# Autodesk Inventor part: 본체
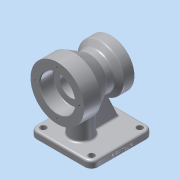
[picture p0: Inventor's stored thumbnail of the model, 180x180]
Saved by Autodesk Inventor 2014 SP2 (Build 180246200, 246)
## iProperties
Created: 2019-01
Part Number: 본체
Material: 알루미늄 6061
Document SubType Name: Modeling
Designer: 거성
Density: 2.71 g/cm^3
Appearance: 알루미늄 - 평지
Mass: 896.056 g
Surface Area: 602.368 cm^2
Volume: 330.648 cm^3
Author: 거성
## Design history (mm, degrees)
sketch "스케치1"
  geometry: L1 (44.102, 40)-(44.102, 15); L2 (39.102, -40)-(39.102, -25); L3 (39.102, -25)-(30.944, -18.154); L4 (30.944, -18.154)-(30.944, -7.791); L5 (30.944, -7.791)-(44.102, 15); L6 (20.102, 20)-(20.102, -23); L7 (24.102, -23)-(24.102, -40); L8 (30.102, 20)-(30.102, 40); L9 (4.102, -40)-(4.102, 40); L10 (20.102, -23)-(24.102, -23); L11 (20.102, 20)-(30.102, 20); L12 (30.102, 40)-(44.102, 40); L13 (39.102, -40)-(24.102, -40)
  constraints: 26 end point, 4 parallel, 3 perpendicular, 2 horizontal
  dimensions: "d2" = 25 distance of L1.start L1.end; "d3" = 30 deg angle of L4 L5; "d4" = 15 distance of L2.start L2.end; "d5" = 50 deg angle of L4 L3; "d6" = 52 diameter of L8 L9; "d7" = 32 diameter of L6 L9; "d8" = 40 diameter of L7 L9; "d9" = 80 vertical distance of L2.start L1.start; "d10" = 20 distance of L8.start L8.end; "d11" = 17 distance of L7.start L7.end; "d20" = 80 distance from line of L9.start L12; "d25" = 80 diameter of L1 L9; "d26" = 70 diameter of L2 L9; "d27" = 13.15845 distance between parallel lines of L4 L1; "d28" = 47.14102 distance from line of L9.end L5
revolve "회전1" sketch "스케치1" stored, may be unused: angle "d23" = 90 deg
sketch "스케치2"
  geometry: C1 r 40 at (0, 0) reference; C2 r 26 at (0, 0) reference; 1 further point
sketch "스케치3" dims "d24" = 66
  geometry: L1 (0, 0)-(0, 33); C1 r 26 at (0, 0) reference; 2 further points
  constraints: 2 coincident, 2 end point, 1 vertical, 1 vertical alignment, 2 other
hole "구멍1" sketch "스케치3" at (0, 33) diameter "d29" = 3.242; stored, may be unused: countersink angle "d33" = 90 deg, drill point angle "d35" = 118 deg; dims "d30" = 9, "d31" = 4, "d32" = 2, "d34" = 11
sketch "스케치4" dims "d39" = 55
  geometry: L1 (0, 0)-(0, 27.5); C1 r 35 at (0, 0) reference; 2 further points
  constraints: 2 coincident, 2 end point, 1 vertical, 1 vertical alignment, 2 other
hole "구멍2" sketch "스케치4" at (0, 27.5) diameter "d40" = 3.242; stored, may be unused: countersink angle "d44" = 90 deg, drill point angle "d46" = 118 deg; dims "d41" = 9, "d42" = 4, "d43" = 2, "d45" = 11
node "작업 평면1"
sketch "스케치7"
  geometry: L1 (-70, -36)-(-70, 36) reference; L2 (-70, 0)-(-70, -33.507); 1 further point
  constraints: 2 end point, 1 collinear, 1 midpoint
chamfer "모따기1" distance "d78" = 1; stored, may be unused: second distance "d79" = 2, angle "d80" = 45 deg
fillet "모깎기2" dims "d81" = 1
fillet "모깎기3" dims "d82" = 0.6
sketch "스케치11"
  geometry: L1 (-75.898, 0)-(-75.898, 35); L2 (-75.898, 35)-(-65.898, 35); L3 (-65.898, 35)-(-65.898, -57); L4 (-65.898, -57)-(-75.898, -57); L5 (-75.898, -57)-(-75.898, 0); L6 (-35.898, 40)-(44.102, 40) reference; L7 (44.102, 15)-(30.944, -7.791) reference; L8 (30.944, -7.791)-(30.944, -18.154) reference; L9 (30.944, -18.154)-(39.102, -25) reference; L10 (39.102, -25)-(39.102, -40) reference; L11 (39.102, -40)-(33.223, -40) reference; L12 (33.223, -40)-(33.223, -29) reference; L13 (33.223, -29)-(31.602, -28.026) reference; L14 (31.602, -28.026)-(29.981, -29) reference; L15 (29.981, -29)-(29.981, -40) reference; L16 (29.981, -40)-(25.102, -40) reference; L17 (25.102, -40)-(24.102, -39) reference; L18 (24.102, -39)-(24.102, -23.6) reference; L19 (23.502, -23)-(20.102, -23) reference; L20 (20.102, -23)-(20.102, 20) reference; L21 (20.102, 20)-(29.102, 20) reference; L22 (30.102, 21)-(30.102, 39) reference; L23 (30.102, 39)-(31.102, 40) reference; L24 (31.102, 40)-(35.481, 40) reference; L25 (35.481, 40)-(35.481, 29) reference; L26 (35.481, 29)-(37.102, 28.026) reference; L27 (37.102, 28.026)-(38.723, 29) reference; L28 (38.723, 29)-(38.723, 40) reference; L29 (38.723, 40)-(44.102, 40) reference; L30 (44.102, 40)-(44.102, 15) reference; L31 (-22.739, -7.791)-(-35.898, 15) reference; L32 (-35.898, 15)-(-35.898, 40) reference; L33 (-35.898, 40)-(-30.519, 40) reference; L34 (-30.519, 40)-(-30.519, 29) reference; L35 (-30.519, 29)-(-28.898, 28.026) reference; L36 (-28.898, 28.026)-(-27.277, 29) reference; L37 (-27.277, 29)-(-27.277, 40) reference; L38 (-27.277, 40)-(-22.898, 40) reference; L39 (-22.898, 40)-(-21.898, 39) reference; L40 (-21.898, 39)-(-21.898, 21) reference; L41 (-20.898, 20)-(-11.898, 20) reference; L42 (-11.898, 20)-(-11.898, -23) reference; L43 (-11.898, -23)-(-15.298, -23) reference; L44 (-15.898, -23.6)-(-15.898, -39) reference; L45 (-15.898, -39)-(-16.898, -40) reference; L46 (-16.898, -40)-(-21.777, -40) reference; L47 (-21.777, -40)-(-21.777, -29) reference; L48 (-21.777, -29)-(-23.398, -28.026) reference; L49 (-23.398, -28.026)-(-25.019, -29) reference; L50 (-25.019, -29)-(-25.019, -40) reference; L51 (-25.019, -40)-(-30.898, -40) reference; L52 (-30.898, -40)-(-30.898, -25) reference; L53 (-30.898, -25)-(-22.739, -18.154) reference; L54 (-22.739, -18.154)-(-22.739, -7.791) reference; L55 (31.102, 40)-(-22.898, 40) reference; L56 (4.102, 40)-(4.102, -40); L57 (5.723, -40)-(2.481, -40) reference; L58 (-75.898, 0)-(4.102, 0); A1 r 0.6 centre (23.502, -23.6) between (24.102, -23.6) and (23.502, -23) reference; A2 r 1 centre (29.102, 21) between (29.102, 20) and (30.102, 21) reference; A3 r 1 centre (-20.898, 21) between (-21.898, 21) and (-20.898, 20) reference; A4 r 0.6 centre (-15.298, -23.6) between (-15.298, -23) and (-15.898, -23.6) reference; 1 further point
  constraints: 14 end point, 3 midpoint, 2 parallel, 1 collinear, 1 perpendicular
  dimensions: "d92" = 5 distance between parallel lines of L2 L6; "d93" = 10 distance of L1.end L2.end; "d94" = 92 distance between parallel lines of L4 L2; "d127" = 80 distance of L1.start L58.end
extrude "돌출5" join sketch "스케치11" stored distance "d95" = 92; taper "d96" = 0 deg
sketch "스케치12"
  geometry: L1 (-65.898, -47)-(-16.918, -24.16); L2 (-16.918, -24.16)-(-16.918, -11); L3 (-30.898, -25)-(39.102, -25) reference; L4 (-16.918, -11)-(-65.898, -11); L5 (-65.898, 35)-(-65.898, -57) reference; L6 (-65.898, -47)-(-65.898, -11); L7 (-65.898, -57)-(-75.898, -57) reference; L8 (-65.898, 35)-(-65.898, 5); L9 (-65.898, 5)-(-65.898, -11); 1 further point
  constraints: 12 end point, 2 perpendicular, 2 point on line, 1 collinear, 1 midpoint
  dimensions: "d97" = 10 distance of L1.start L5.end; "d98" = 25 deg angle of L7 L1; "d99" = 48.97999 distance of L2.end L4.end; "d100" = 36 distance of L4.end L1.start; "d128" = 30 distance of L5.start L8.end; "d129" = 16 distance of L8.end L9.end
extrude "돌출6" join sketch "스케치12" stored distance "d101" = 10; taper "d102" = 0 deg
sketch "스케치13"
  geometry: L1 (92, 0)-(0, 0) reference; L2 (0, 0)-(0, 92) reference; C1 r 16 at (46, 30); 1 further point
  constraints: 1 centre point
  dimensions: "d103" = 32 diameter of C1; "d104" = 30 distance from line of L1 C1.centre; "d105" = 46 distance from line of C1.centre L2
extrude "돌출7" join sketch "스케치13" stored distance "d106" = 40; taper "d107" = 0 deg
fillet "모깎기8" dims "d108" = 3
fillet "모깎기9" dims "d109" = 3
fillet "모깎기10" dims "d110" = 3
fillet "모깎기11" dims "d111" = 10
sketch "스케치14"
  geometry: C1 r 4.5 at (0, 82); A1 r 10 centre (0, 82) between (0, 92) and (-10, 82) reference; 1 further point
  constraints: 1 centre point, 1 coincident
  dimensions: "d112" = 9 diameter of C1
extrude "돌출8" cut sketch "스케치14" stored distance "d113" = 10; taper "d114" = 0 deg
fillet "모깎기12" dims "d121" = 3
sketch "스케치15"
  geometry: L1 (-25, -75.898)-(47, -75.898) reference; L2 (-35, -65.898)-(-35, -75.898) reference; 2 further points
  constraints: 1 other
  dimensions: "d122" = 46 distance from line of L2 point (11, -71.898); "d123" = 4 distance from line of L1 point (11, -71.898)
feature "엠보싱2" sketch "스케치15" dims "d124" = 0.5, "d125" = 0
fillet "모깎기13" dims "d126" = 3
sketch "스케치16"
  geometry: L1 (31, 43)-(41, 43); L2 (41, 43)-(41, 41.881); L3 (41, 41.881)-(31, 41.881); L4 (31, 41.881)-(31, 43); 1 further point
  constraints: 8 end point, 2 parallel, 1 horizontal, 1 perpendicular
extrude "돌출9" join sketch "스케치16" distance "d130" = 48; taper "d131" = 0 deg
fillet "모깎기14" dims "d132" = 3
fillet "모깎기15" dims "d133" = 3
fillet "모깎기16" dims "d134" = 3
node "솔리드1"
pattern_circular "원형 패턴1" dims angle "d37" = 360 deg
pattern_circular "원형 패턴2" dims angle "d48" = 360 deg
pattern_linear "직사각형 패턴1" dims "d117" = 72, "d120" = 72
node "절단 모서리 투영1"
